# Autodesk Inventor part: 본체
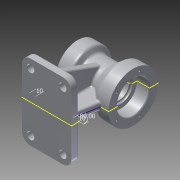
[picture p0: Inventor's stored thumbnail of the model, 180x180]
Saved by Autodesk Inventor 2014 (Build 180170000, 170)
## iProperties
Created: 2015-08
Part Number: 본체
Material: 알루미늄 6061
Document SubType Name: Modeling
Designer: Owner
Density: 2.71 g/cm^3
Appearance: 알루미늄 - 평지
Mass: 1062.79 g
Surface Area: 749.652 cm^2
Volume: 392.172 cm^3
Author: Owner
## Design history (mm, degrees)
sketch "스케치1"
  geometry: L1 (-45, 0)-(45, 0); L2 (-45, 20)-(-45, 35); L3 (-45, 35)-(-25, 35); L4 (-25, 35)-(-19.804, 26); L5 (-19.804, 26)-(8.315, 26); L6 (8.315, 26)-(25, 40); L7 (25, 40)-(45, 40); L8 (45, 40)-(45, 26); L9 (45, 26)-(25, 26); L10 (22, 16)-(-28, 16); L11 (-28, 20)-(-45, 20); L12 (-28, 20)-(-28, 16); L13 (25, 26)-(25, 19); L14 (25, 19)-(22, 19); L15 (22, 19)-(22, 16); 2 further points
  constraints: 30 end point, 8 parallel, 4 perpendicular, 2 vertical alignment, 1 coincident, 1 horizontal, 1 midpoint
  dimensions: "d0" = 90 distance of L1.start L1.end; "d1" = 20 distance of L2.end L3.end; "d2" = 20 distance of L6.end L7.end; "d3" = 70 diameter of L3 L1; "d4" = 80 diameter of L7 L1; "d5" = 52 diameter of L5 L1; "d6" = 60 deg angle of L4 L5; "d7" = 40 deg angle of L5 L6; "d8" = 40 diameter of L11 L1; "d9" = 17 distance from line of L1.start L12; "d10" = 32 diameter of L10 L1; "d11" = 38 diameter of L14 L1; "d12" = 3 distance of L13.end L14.end; "d13" = 20 distance of L8.end L9.end; "d14" = 52 diameter of L9 L1
revolve "회전1" sketch "스케치1" stored, may be unused: angle "d15" = 90 deg
node "작업 평면1"
sketch "스케치2"
  geometry: L1 (25, 35)-(25, -35) reference; L2 (45, 35)-(45, -35) reference; L3 (45, 35)-(45, -35) reference; L4 (45, 35)-(25, 35) reference; L5 (45, -35)-(25, -35) reference; L6 (-35, 61)-(45, 61); L7 (45, 61)-(45, -61); L8 (45, -61)-(-35, -61); L9 (-35, -61)-(-35, 61); 2 further points
  constraints: 8 end point, 2 parallel, 1 collinear, 1 horizontal, 1 horizontal alignment, 1 midpoint, 1 perpendicular
  dimensions: "d17" = 80 distance of L7.end L8.end; "d18" = 122 distance of L6.end L7.end
extrude "돌출1" join sketch "스케치2" distance "d20" = 12; taper "d21" = 0 deg
node "작업 평면2"
sketch "스케치3"
  geometry: L1 (0, 0)-(0, 12) reference; L2 (0, 12)-(122, 12) reference; L3 (122, 12)-(122, 0) reference; L4 (122, 0)-(0, 0) reference; L5 (61, -26)-(61, 156) reference; L6 (10, 12)-(35.909, 83.185); L7 (86.091, 83.185)-(112, 12); C1 r 16 at (61, 90) reference; A1 r 26 centre (61, 90) between (35.909, 83.185) and (86.091, 83.185) reference; 1 further point
  constraints: 4 end point, 2 point on circle, 2 point on line
  dimensions: "d22" = 70 deg angle of L2 L6; "d23" = 10 distance of L6.start L1.end; "d24" = 70 deg angle of L7 L2; "d25" = 10 distance of L7.end L2.end
extrude "돌출2" join sketch "스케치3" stored distance "d26" = 12; taper "d27" = 0 deg
sketch "스케치4"
  geometry: L1 (35, 61)-(-45, 61) reference; L2 (-45, 61)-(-45, -61) reference; C1 r 6 at (-31, 47); 1 further point
  constraints: 1 centre point
  dimensions: "d28" = 12 diameter of C1; "d29" = 14 distance from line of C1.centre L1; "d30" = 14 distance from line of C1.centre L2
extrude "돌출3" cut sketch "스케치4" stored distance "d31" = 12; taper "d32" = 0 deg
fillet "모깎기1" dims "d39" = 14
node "작업 평면3"
sketch "스케치5"
  geometry: L1 (-14, 125)-(6, 125) reference; L2 (6, 125)-(11.196, 116) reference; L3 (11.196, 116)-(39.315, 116) reference; L4 (39.315, 116)-(56, 130) reference; L5 (56, 130)-(76, 130) reference; L6 (76, 130)-(76, 116) reference; L7 (76, 116)-(56, 116) reference; L8 (56, 116)-(56, 109) reference; L9 (56, 109)-(53, 109) reference; L10 (53, 109)-(53, 106) reference; L11 (53, 106)-(3, 106) reference; L12 (3, 106)-(3, 110) reference; L13 (3, 110)-(-14, 110) reference; L14 (-14, 110)-(-14, 125) reference; L15 (6, 55)-(-14, 55) reference; L16 (-14, 55)-(-14, 70) reference; L17 (-14, 70)-(3, 70) reference; L18 (3, 70)-(3, 74) reference; L19 (3, 74)-(53, 74) reference; L20 (53, 74)-(53, 71) reference; L21 (53, 71)-(56, 71) reference; L22 (56, 71)-(56, 64) reference; L23 (56, 64)-(76, 64) reference; L24 (76, 64)-(76, 50) reference; L25 (76, 50)-(56, 50) reference; L26 (56, 50)-(39.315, 64) reference; L27 (39.315, 64)-(32, 64) reference; L28 (32, 64)-(32, 12) reference; L29 (32, 12)-(66, 12) reference; L30 (66, 12)-(66, 0) reference; L31 (66, 0)-(-14, 0) reference; L32 (-14, 0)-(-14, 12) reference; L33 (-14, 12)-(20, 12) reference; L34 (20, 12)-(20, 64) reference; L35 (20, 64)-(11.196, 64) reference; L36 (11.196, 64)-(6, 55) reference; L37 (-14, 125)-(6, 125) reference; L38 (6, 125)-(11.196, 116) reference; L39 (11.196, 116)-(39.315, 116) reference; L40 (39.315, 116)-(56, 130) reference; L41 (56, 130)-(76, 130) reference; L42 (76, 130)-(76, 116) reference; L43 (76, 116)-(56, 116) reference; L44 (56, 116)-(56, 109) reference; L45 (56, 109)-(53, 109) reference; L46 (53, 109)-(53, 106) reference; L47 (53, 106)-(3, 106) reference; L48 (3, 106)-(3, 110) reference; L49 (3, 110)-(-14, 110) reference; L50 (-14, 110)-(-14, 125) reference; L51 (6, 55)-(-14, 55) reference; L52 (-14, 55)-(-14, 70) reference; L53 (-14, 70)-(3, 70) reference; L54 (3, 70)-(3, 74) reference; L55 (3, 74)-(53, 74) reference; L56 (53, 74)-(53, 71) reference; L57 (53, 71)-(56, 71) reference; L58 (56, 71)-(56, 64) reference; L59 (56, 64)-(76, 64) reference; L60 (76, 64)-(76, 50) reference; L61 (76, 50)-(56, 50) reference; L62 (56, 50)-(39.315, 64) reference; L63 (39.315, 64)-(32, 64) reference; L64 (32, 64)-(32, 12) reference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; 1 further point
  constraints: 4 end point, 3 point on line, 1 midpoint, 1 perpendicular
  dimensions: "d40" = 10 distance from line of L32 L73.start; "d41" = 10 distance from line of L74.start L30; "d42" = 80 deg angle of L74 L29
  node "절단 모서리 투영2"
  node "절단 모서리 투영3"
feature "리브1" dims "d43" = 1, "d44" = 12, "d45" = 0, "d46" = 0, "d47" = 1, "d48" = 1
feature "리브2" dims "d49" = 1, "d50" = 12, "d51" = 0, "d52" = 0, "d53" = 1, "d54" = 1
sketch "스케치6"
  geometry: C1 r 40 at (0, 0) reference; 1 further point
  constraints: 1 vertical alignment
  dimensions: "d55" = 33 distance of point (0, 33) C1.centre
hole "구멍1" sketch "스케치6" at (0, 33) diameter "d56" = 3.242; stored, may be unused: countersink angle "d60" = 90 deg, drill point angle "d62" = 118 deg; dims "d57" = 10, "d58" = 4, "d59" = 2, "d61" = 13
sketch "스케치7"
  geometry: C1 r 35 at (0, 0) reference; 1 further point
  constraints: 1 vertical alignment
  dimensions: "d66" = 27 distance of point (0, 27) C1.centre
hole "구멍2" sketch "스케치7" at (0, 27) diameter "d67" = 3.242; stored, may be unused: countersink angle "d71" = 90 deg, drill point angle "d73" = 118 deg; dims "d68" = 10, "d69" = 4, "d70" = 2, "d72" = 13
sketch "스케치8"
  geometry: L1 (112, 12)-(67, 12) reference; L2 (43, 30)-(43, 36); L3 (31, 30)-(31, 36); L4 (14, 12)-(108, 12) reference; A1 r 26 centre (61, 90) between (67, 64.702) and (86.091, 83.185) reference; A2 r 6 centre (37, 30) between (31, 30) and (43, 30); A3 r 6 centre (37, 36) between (43, 36) and (31, 36)
  constraints: 4 end point, 4 point on circle, 2 centre point, 2 tangent, 1 parallel, 1 perpendicular, 1 vertical alignment
  dimensions: "d77" = 12 diameter of A2; "d78" = 12 diameter of A3; "d79" = 24 horizontal distance of A3.centre A1.centre; "d80" = 18 distance from line of A2.centre L4; "d81" = 18 dimension on A2 A3
extrude "돌출4" cut sketch "스케치8" stored distance "d82" = 12; taper "d83" = 0 deg
node "작업 평면4"
fillet "모깎기2" dims "d84" = 0.3
chamfer "모따기1" distance "d85" = 1; stored, may be unused: second distance "d86" = 2, angle "d87" = 45 deg
fillet "모깎기3" dims "d88" = 3
fillet "모깎기4" dims "d89" = 3
fillet "모깎기5" dims "d90" = 5
fillet "모깎기6" dims "d91" = 3
sketch "스케치9"
  geometry: L1 (-3, 37.119)-(-3, 0) reference; L2 (53, -3)-(1, -3) reference; 2 further points
  constraints: 1 other
  dimensions: "d92" = 16 distance from line of point (13, 21) L1; "d93" = 24 distance from line of point (13, 21) L2
feature "엠보싱1" sketch "스케치9" dims "d0" = 90, "d1" = 20, "d2" = 20, "d3" = 70, "d4" = 80, "d5" = 52, "d6" = 60 deg, "d7" = 40 deg, "d8" = 40, "d9" = 17, "d10" = 32, "d11" = 38, "d12" = 3, "d13" = 20, "d14" = 52, "d94" = 0.5, "d95" = 0
fillet "모깎기7" dims "d96" = 3
node "솔리드1"
pattern_linear "직사각형 패턴1" dims "d35" = 52, "d38" = 94
pattern_circular "원형 패턴1" dims angle "d64" = 360 deg
pattern_circular "원형 패턴2" dims angle "d75" = 360 deg
mirror "대칭1"
node "투영된 루프1"
node "절단 모서리 투영1"
